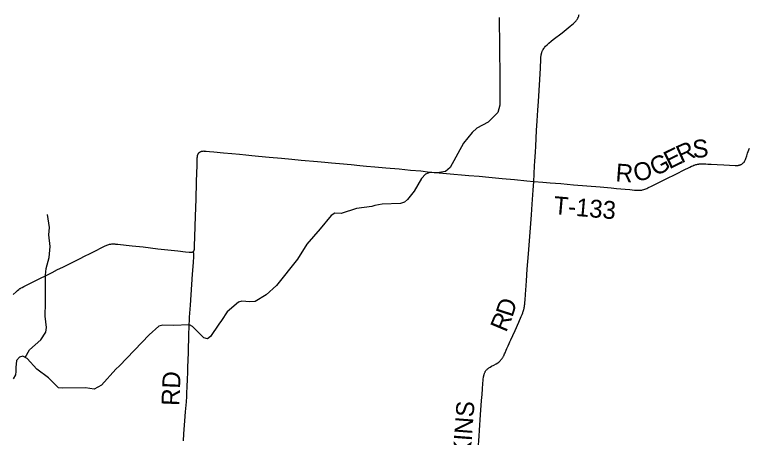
# Model space of a CAD drawing. Extents: x -49 to -8.2, y 9.4 to 23.5.
# Drawn here: x -11.642 to -10.474, y 13.23 to 13.902 of the extents above; entities that cross this region are included whole.
import ezdxf

# ---------------------------------------------------------------- set-up
doc = ezdxf.new("R2010")
doc.units = 0
for name, color, linetype in [('GM_X_County_Road', 7, 'Continuous'), ('GM_X_Major_River', 7, 'Continuous'), ('GM_X_Minor_River', 7, 'Continuous'), ('GM_X_Township_Road', 7, 'Continuous'), ('GM_X_Township_Road_Text', 7, 'Continuous')]:
    doc.layers.add(name, color=color, linetype=linetype)

msp = doc.modelspace()

# ---------------------------------------------------------------- linework, layer by layer
at = {"layer": 'GM_X_County_Road'}
for points in [[(-11.3583, 13.5254), (-11.358, 13.5256), (-11.3577, 13.5259), (-11.3573, 13.5262), (-11.357, 13.5266), (-11.3568, 13.5269), (-11.3566, 13.5273), (-11.3565, 13.5276), (-11.3563, 13.5281), (-11.3562, 13.5285), (-11.3561, 13.5301), (-11.3559, 13.5345), (-11.3554, 13.5491), (-11.3548, 13.5652), (-11.3543, 13.582), (-11.3535, 13.609), (-11.3528, 13.636), (-11.3523, 13.6512), (-11.352, 13.6612), (-11.3518, 13.6677), (-11.3517, 13.673), (-11.3516, 13.6746), (-11.3515, 13.6759), (-11.3514, 13.6769), (-11.3512, 13.6779), (-11.351, 13.6787), (-11.3508, 13.6793), (-11.3506, 13.6798), (-11.3504, 13.6803), (-11.3502, 13.6809), (-11.3499, 13.6814), (-11.3495, 13.6818), (-11.3491, 13.6823), (-11.3486, 13.6828), (-11.3482, 13.6832), (-11.3477, 13.6836), (-11.3472, 13.684), (-11.3467, 13.6843), (-11.3462, 13.6846), (-11.3456, 13.6848), (-11.3451, 13.685), (-11.3444, 13.6852), (-11.3436, 13.6853), (-11.343, 13.6854), (-11.3422, 13.6854), (-11.3414, 13.6855), (-11.3404, 13.6854), (-11.3394, 13.6854), (-11.3373, 13.6852), (-11.3324, 13.6847), (-11.3252, 13.684), (-11.3098, 13.6826), (-11.2967, 13.6814), (-11.2847, 13.6802), (-11.2745, 13.6792), (-11.2646, 13.6782), (-11.2541, 13.6772), (-11.2374, 13.6756), (-11.2177, 13.6739), (-11.2012, 13.6724), (-11.1866, 13.6711), (-11.1603, 13.6687), (-11.1488, 13.6676), (-11.1384, 13.6666), (-11.1257, 13.6654), (-11.1069, 13.6637), (-11.0929, 13.6624), (-11.0827, 13.6615), (-11.0694, 13.6603), (-11.052, 13.6588), (-11.0308, 13.6569), (-11.0125, 13.6552), (-10.9963, 13.6537), (-10.982, 13.6519), (-10.9784, 13.6515), (-10.9749, 13.6512), (-10.967, 13.6505), (-10.9553, 13.6496), (-10.92, 13.6466), (-10.9036, 13.6452), (-10.8878, 13.6437), (-10.8671, 13.6418), (-10.8474, 13.6399), (-10.8274, 13.6379), (-10.8167, 13.637)], [(-11.6443, 13.4572), (-11.6398, 13.4612), (-11.6372, 13.4636), (-11.6354, 13.465), (-11.6341, 13.466), (-11.6335, 13.4665), (-11.6328, 13.467), (-11.6314, 13.4679), (-11.6301, 13.4686), (-11.6273, 13.4701), (-11.6242, 13.4717), (-11.6208, 13.4733), (-11.6117, 13.4778), (-11.602, 13.4826), (-11.592, 13.4876), (-11.5825, 13.4924), (-11.5736, 13.4968), (-11.5655, 13.5007), (-11.5549, 13.506), (-11.5379, 13.5145), (-11.5307, 13.5181), (-11.5219, 13.5225), (-11.5114, 13.5278), (-11.5055, 13.5308), (-11.498, 13.5345), (-11.4966, 13.5351), (-11.4952, 13.5358), (-11.4938, 13.5363), (-11.4924, 13.5367), (-11.4912, 13.537), (-11.4906, 13.5372), (-11.4901, 13.5372), (-11.4889, 13.5374), (-11.4876, 13.5376), (-11.4865, 13.5377), (-11.4855, 13.5377), (-11.4845, 13.5377), (-11.4829, 13.5376), (-11.4815, 13.5375), (-11.4803, 13.5374), (-11.4777, 13.5372), (-11.4647, 13.5358), (-11.455, 13.5348), (-11.4375, 13.5328), (-11.4141, 13.53), (-11.3984, 13.5283), (-11.3823, 13.5265), (-11.3703, 13.5251), (-11.3644, 13.5245), (-11.3631, 13.5244), (-11.362, 13.5243), (-11.361, 13.5243), (-11.3605, 13.5244), (-11.36, 13.5245), (-11.3595, 13.5246), (-11.3591, 13.5248), (-11.3587, 13.5251), (-11.3583, 13.5254)]]:
    msp.add_lwpolyline(points, dxfattribs=at)
at = {"layer": 'GM_X_Major_River'}
msp.add_lwpolyline([(-10.8714, 13.8975), (-10.8706, 13.8021), (-10.8708, 13.7583), (-10.8738, 13.7466), (-10.8891, 13.7315), (-10.907, 13.722), (-10.9144, 13.7149), (-10.9283, 13.6981), (-10.9497, 13.6592), (-10.9567, 13.6529), (-10.9696, 13.6509), (-10.9817, 13.651), (-10.9885, 13.6485), (-10.9951, 13.6418), (-11.0065, 13.6217), (-11.0171, 13.6084), (-11.022, 13.6043), (-11.0284, 13.6018), (-11.0576, 13.6011), (-11.0692, 13.5986), (-11.0743, 13.5972), (-11.0984, 13.5939), (-11.1228, 13.5861), (-11.133, 13.5864), (-11.1385, 13.5831), (-11.156, 13.5617), (-11.1775, 13.5372), (-11.1925, 13.5132), (-11.2255, 13.4715), (-11.2419, 13.4565), (-11.2597, 13.4462), (-11.2682, 13.4453), (-11.2807, 13.4465), (-11.2858, 13.445), (-11.3043, 13.4298), (-11.3133, 13.4156), (-11.3172, 13.4098), (-11.3304, 13.3903), (-11.3352, 13.3866), (-11.3414, 13.3882), (-11.359, 13.4065), (-11.3639, 13.4092), (-11.3898, 13.408), (-11.4063, 13.4082), (-11.4129, 13.4068), (-11.4283, 13.3932), (-11.4753, 13.3437), (-11.4809, 13.3385), (-11.5037, 13.3131), (-11.5158, 13.3069), (-11.5292, 13.3087), (-11.5662, 13.3083), (-11.5721, 13.3088), (-11.5884, 13.3249), (-11.6065, 13.3386), (-11.6219, 13.3554), (-11.6288, 13.3589), (-11.6345, 13.3575), (-11.6388, 13.3521), (-11.6399, 13.3413), (-11.6401, 13.3349), (-11.6407, 13.3294), (-11.6443, 13.3232)], dxfattribs=at)
at = {"layer": 'GM_X_Minor_River'}
msp.add_lwpolyline([(-11.6251, 13.357), (-11.6181, 13.3693), (-11.6002, 13.3852), (-11.5924, 13.3972), (-11.5915, 13.4048), (-11.5935, 13.4228), (-11.5931, 13.4437), (-11.5927, 13.4878), (-11.5916, 13.4984), (-11.5871, 13.5158), (-11.5856, 13.5337), (-11.5876, 13.5523), (-11.5868, 13.5635), (-11.5895, 13.5843)], dxfattribs=at)
at = {"layer": 'GM_X_Township_Road'}
for points in [[(-10.8167, 13.637), (-10.8159, 13.6487), (-10.8152, 13.6626), (-10.8149, 13.6688), (-10.814, 13.684), (-10.8135, 13.6927), (-10.8126, 13.7057), (-10.812, 13.7178), (-10.811, 13.7333), (-10.81, 13.7501), (-10.8092, 13.7643), (-10.8071, 13.7991), (-10.8061, 13.8174), (-10.8054, 13.8313), (-10.8053, 13.8335), (-10.8051, 13.8355), (-10.8049, 13.8369), (-10.8047, 13.8381), (-10.8046, 13.8389), (-10.8045, 13.8395), (-10.8043, 13.8402), (-10.8042, 13.841), (-10.8039, 13.8418), (-10.8036, 13.8428), (-10.8033, 13.8435), (-10.8031, 13.8442), (-10.8027, 13.845), (-10.8024, 13.8456), (-10.8021, 13.8463), (-10.8017, 13.8468), (-10.8013, 13.8475), (-10.8009, 13.8482), (-10.8002, 13.8491), (-10.7996, 13.8499), (-10.7978, 13.852), (-10.7953, 13.8545), (-10.7925, 13.8569), (-10.7889, 13.8599), (-10.7855, 13.8626), (-10.7716, 13.8736), (-10.7587, 13.8838), (-10.7533, 13.8882), (-10.7517, 13.8897), (-10.7508, 13.8906), (-10.7502, 13.8912), (-10.7497, 13.8918), (-10.7491, 13.8925), (-10.7485, 13.8933), (-10.748, 13.894), (-10.7477, 13.8946), (-10.7471, 13.8955), (-10.7467, 13.8963), (-10.7463, 13.8971), (-10.746, 13.8977), (-10.7458, 13.8982), (-10.7455, 13.899), (-10.7452, 13.8997), (-10.7449, 13.9007), (-10.7447, 13.9015), (-10.7445, 13.9024)], [(-10.8167, 13.637), (-10.8022, 13.636), (-10.7904, 13.635), (-10.7733, 13.6336), (-10.7532, 13.6318), (-10.7323, 13.6301), (-10.711, 13.6282), (-10.6937, 13.6267), (-10.6848, 13.6259), (-10.6715, 13.6248), (-10.6641, 13.6241), (-10.6563, 13.6234), (-10.6528, 13.6232), (-10.6509, 13.6231), (-10.6494, 13.623), (-10.648, 13.623), (-10.6473, 13.623), (-10.6468, 13.6231), (-10.6462, 13.6231), (-10.6458, 13.6232), (-10.645, 13.6233), (-10.6439, 13.6236), (-10.6416, 13.6242), (-10.6401, 13.6246), (-10.6384, 13.6253), (-10.6368, 13.6259), (-10.635, 13.6268), (-10.6283, 13.6301), (-10.6221, 13.633), (-10.6082, 13.6399), (-10.5885, 13.6498), (-10.5785, 13.6548), (-10.5687, 13.6596), (-10.5656, 13.6611), (-10.5636, 13.662), (-10.5619, 13.6627), (-10.5611, 13.663), (-10.5602, 13.6633), (-10.5591, 13.6637), (-10.5579, 13.664), (-10.5571, 13.6642), (-10.5561, 13.6644), (-10.5552, 13.6646), (-10.5543, 13.6647), (-10.5535, 13.6648), (-10.5523, 13.6649), (-10.5508, 13.665), (-10.5484, 13.665), (-10.5457, 13.665), (-10.543, 13.6649), (-10.54, 13.6647), (-10.5344, 13.6644), (-10.5248, 13.6639), (-10.5146, 13.6635), (-10.5052, 13.663), (-10.4963, 13.6626), (-10.4932, 13.6625), (-10.4925, 13.6626), (-10.4918, 13.6626), (-10.4911, 13.6627), (-10.4901, 13.6629), (-10.4895, 13.663), (-10.4889, 13.6632), (-10.4881, 13.6635), (-10.4872, 13.6638), (-10.4866, 13.6641), (-10.486, 13.6645), (-10.4853, 13.6649), (-10.4846, 13.6655), (-10.4841, 13.6659), (-10.4835, 13.6665), (-10.4828, 13.6672), (-10.4822, 13.6679), (-10.4818, 13.6684), (-10.4814, 13.6692), (-10.4809, 13.67), (-10.4805, 13.6709), (-10.48, 13.6721), (-10.4794, 13.6734), (-10.4779, 13.6779), (-10.4766, 13.6818), (-10.4737, 13.6898)], [(-10.9051, 13.2107), (-10.9035, 13.2321), (-10.9028, 13.2414), (-10.9011, 13.2658), (-10.8995, 13.2885), (-10.8988, 13.2981), (-10.8981, 13.3071), (-10.8975, 13.3157), (-10.8971, 13.3209), (-10.8968, 13.3233), (-10.8966, 13.325), (-10.8963, 13.3264), (-10.8961, 13.3277), (-10.8958, 13.3287), (-10.8956, 13.3296), (-10.8953, 13.3305), (-10.895, 13.3315), (-10.8947, 13.3322), (-10.8944, 13.3331), (-10.8941, 13.3338), (-10.8937, 13.3346), (-10.8932, 13.3354), (-10.8927, 13.3361), (-10.8922, 13.3367), (-10.8915, 13.3374), (-10.8908, 13.3381), (-10.89, 13.3389), (-10.889, 13.3397), (-10.888, 13.3405), (-10.8872, 13.3411), (-10.886, 13.3418), (-10.8836, 13.3431), (-10.88, 13.3449), (-10.8764, 13.3468), (-10.8736, 13.3487), (-10.8721, 13.3498), (-10.8711, 13.3506), (-10.8703, 13.3514), (-10.8695, 13.3523), (-10.8688, 13.3531), (-10.8682, 13.3539), (-10.8676, 13.3547), (-10.867, 13.3555), (-10.8664, 13.3564), (-10.8659, 13.3572), (-10.8655, 13.358), (-10.8649, 13.3589), (-10.8644, 13.3599), (-10.8638, 13.361), (-10.863, 13.3627), (-10.8621, 13.3646), (-10.8603, 13.3689), (-10.8592, 13.3714), (-10.8573, 13.3757), (-10.8558, 13.3791), (-10.8545, 13.3819), (-10.8531, 13.385), (-10.8501, 13.3919), (-10.8464, 13.4001), (-10.8404, 13.4134), (-10.8366, 13.4223), (-10.8353, 13.4254), (-10.8341, 13.4283), (-10.8333, 13.4306), (-10.833, 13.4314), (-10.8328, 13.4321), (-10.8326, 13.4328), (-10.8324, 13.4334), (-10.8322, 13.4341), (-10.8321, 13.4347), (-10.8318, 13.4359), (-10.8316, 13.4368), (-10.8314, 13.4379), (-10.8312, 13.4388), (-10.8311, 13.4396), (-10.8311, 13.4402), (-10.8308, 13.4419), (-10.8306, 13.4446), (-10.8303, 13.4483), (-10.8297, 13.4577), (-10.8293, 13.4641), (-10.8283, 13.4788), (-10.827, 13.4976), (-10.8252, 13.5218), (-10.8231, 13.5493), (-10.8204, 13.584), (-10.8192, 13.6007), (-10.8177, 13.6231), (-10.8167, 13.637)], [(-11.3737, 13.2245), (-11.3729, 13.2354), (-11.3712, 13.2561), (-11.3702, 13.2706), (-11.3689, 13.2865), (-11.3684, 13.2951), (-11.368, 13.302), (-11.3676, 13.3094), (-11.3671, 13.3234), (-11.3668, 13.3321), (-11.3665, 13.3417), (-11.3658, 13.3647), (-11.3654, 13.3755), (-11.3651, 13.3836), (-11.3648, 13.3969), (-11.3646, 13.4032), (-11.3643, 13.4097), (-11.3641, 13.4156), (-11.3637, 13.421), (-11.3624, 13.4401), (-11.3613, 13.4568), (-11.359, 13.4893), (-11.3577, 13.5083), (-11.357, 13.5175), (-11.3569, 13.5205), (-11.3569, 13.5212), (-11.3569, 13.5217), (-11.3569, 13.5221), (-11.357, 13.5225), (-11.3571, 13.5228), (-11.3577, 13.524), (-11.3583, 13.5254)]]:
    msp.add_lwpolyline(points, dxfattribs=at)

# ---------------------------------------------------------------- texts
at = {"layer": 'GM_X_Township_Road_Text'}
for s, height, rotation, p in [('S', 0.0284, 4.4279, (-10.5632, 13.6742)), ('E', 0.0284, 26.1722, (-10.6009, 13.6561)), ('R', 0.0284, 23.8725, (-10.5821, 13.6654)), ('G', 0.0284, 27.5723, (-10.6229, 13.6446)), ('O', 0.0284, 13.114, (-10.6546, 13.6362)), ('R', 0.0284, 355.683, (-10.6872, 13.6373)), ('T-133', 0.02841, 354.9573, (-10.7861, 13.5854)), ('D', 0.0284, 71.9316, (-10.8507, 13.4198)), ('R', 0.0284, 67.2462, (-10.8606, 13.3959)), ('RD', 0.02841, 87.6543, (-11.3802, 13.2797)), ('WATKINS', 0.02841, 85.7018, (-10.9236, 13.1141))]:
    msp.add_text(s, height=height, rotation=rotation, dxfattribs=at).set_placement(p)

doc.saveas('drawing.dxf')
